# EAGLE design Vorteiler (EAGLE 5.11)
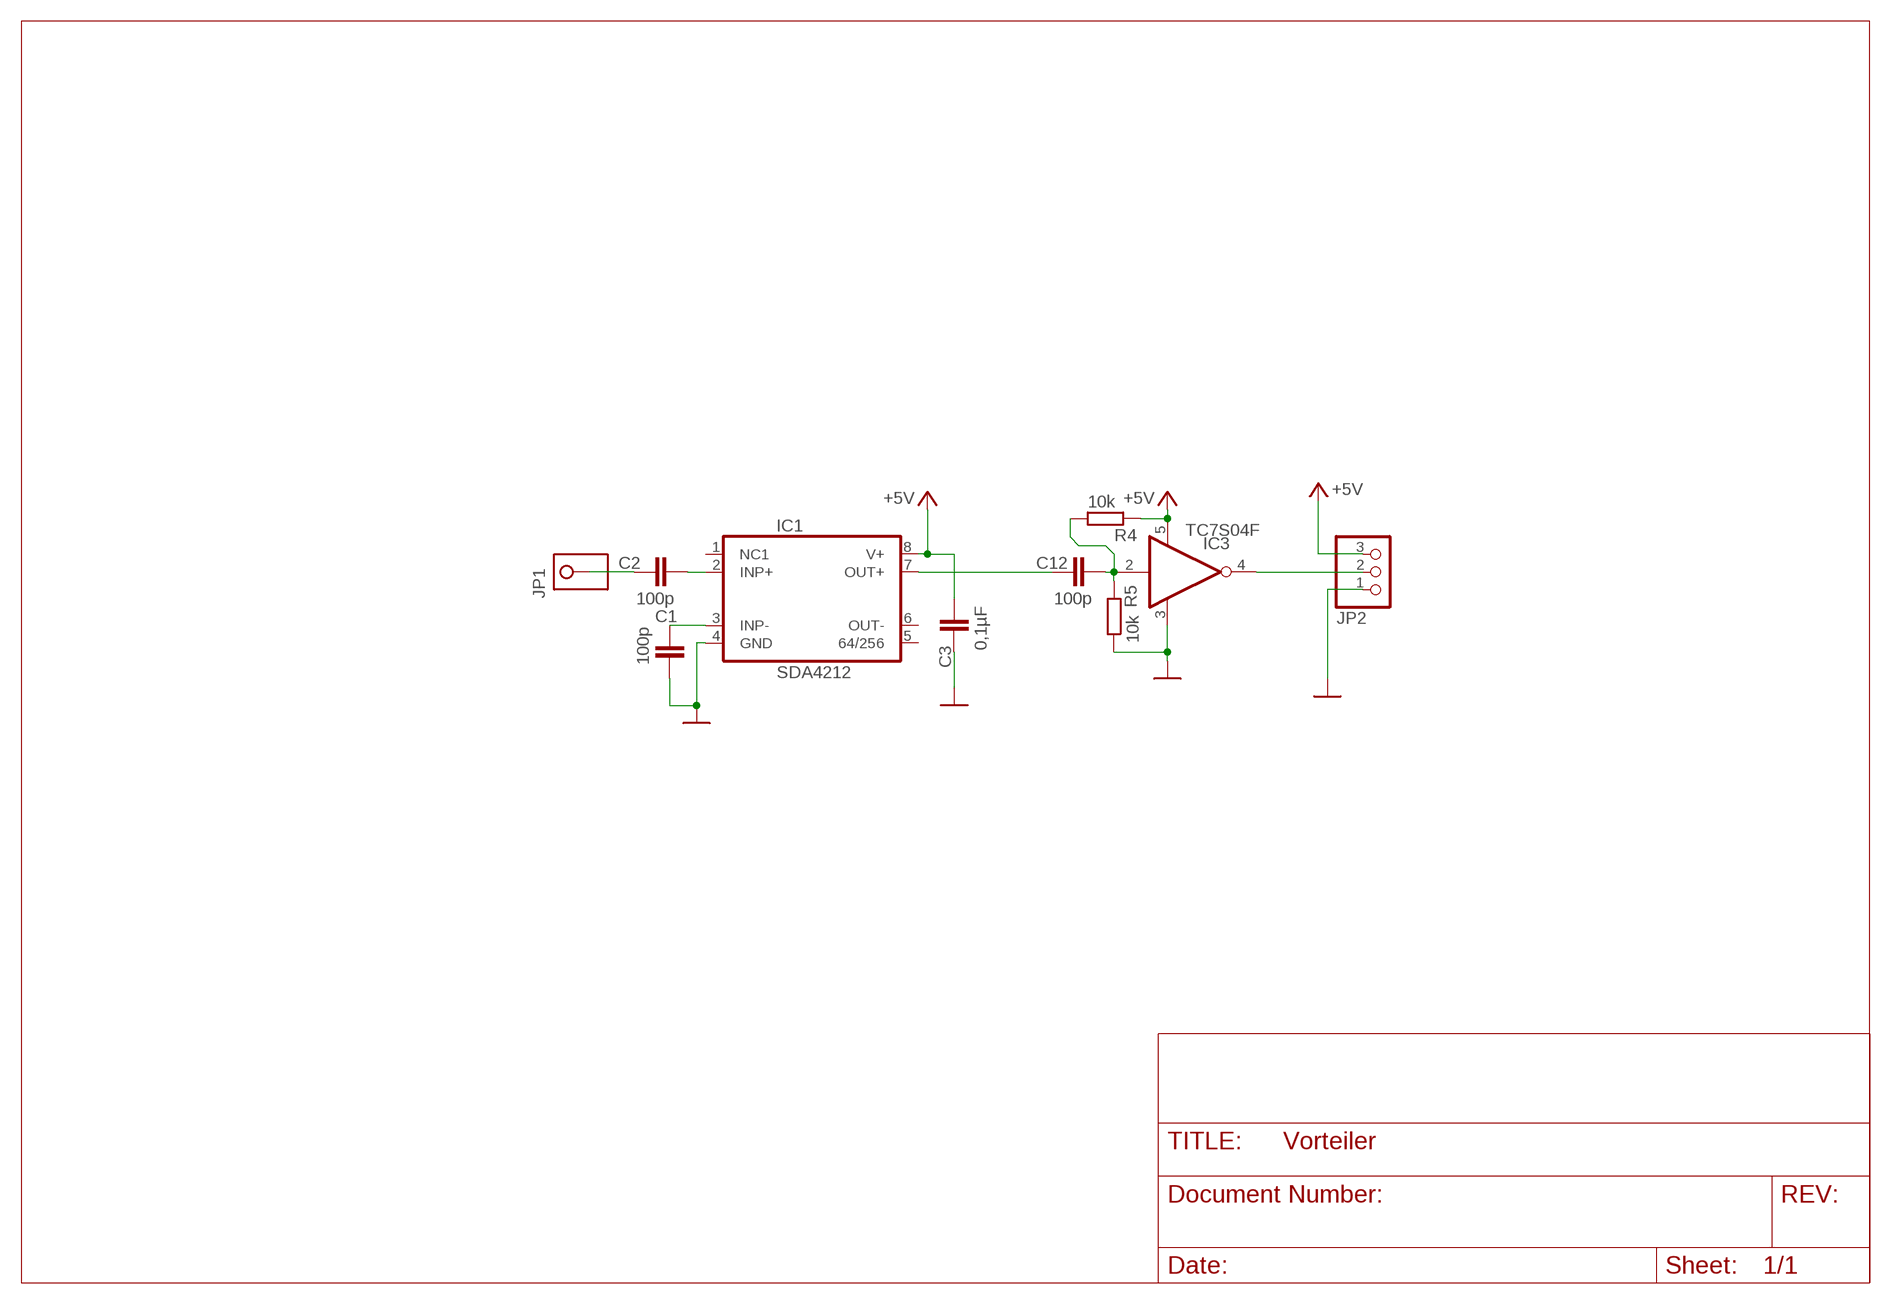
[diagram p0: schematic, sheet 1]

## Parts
C1  100p  C-EUC0805  [C0805]
C2  100p  C-EUC0805  [C0805]
C3  0,1µF  C-EUC0805  [C0805]
C12  100p  C-EUC0805  [C0805]
IC1  SDA4212  [DIL8]
IC3  TC7S04F  [SSOP5]
JP1  LÖTPUNKT1  [PUNKT1]
JP2  PINHD-1X03_2.54-90°  [1X03/90]
R4  10k  R-EU_R0805  [R0805]
R5  10k  R-EU_R0805  [R0805]

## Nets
+5V: C3.1 IC1.8(V+) IC3.5(VCC) JP2.3 R4.2
GND: C1.1 C3.2 IC1.4(GND) IC3.3(GND) JP2.1 R5.1
N$1: C12.2 IC1.7(OUT+)
N$2: C12.1 IC3.2(I) R4.1 R5.2
N$3: C1.2 IC1.3(INP-)
N$5: C2.1 IC1.2(INP+)
N$6: C2.2 JP1.P$1
N$7: IC3.4(O) JP2.2
Unconnected: IC1.1(NC1) IC1.5(64/256) IC1.6(OUT-)

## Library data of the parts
C1-C3 C12 = rcl:C-EU: CAPACITOR, European symbol
IC1 = 1Eigene:SDA4212
IC3 = 1Eigene:TC7S04F
JP1 = 1Eigene:LÖTPUNKT1
JP2 = pinhead-2:PINHD-1X03: PIN HEADER
R4 R5 = rcl:R-EU_: RESISTOR, European symbol

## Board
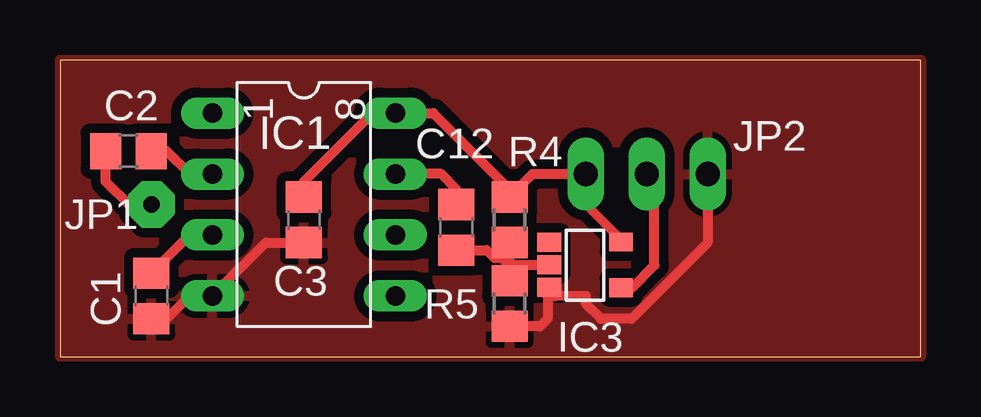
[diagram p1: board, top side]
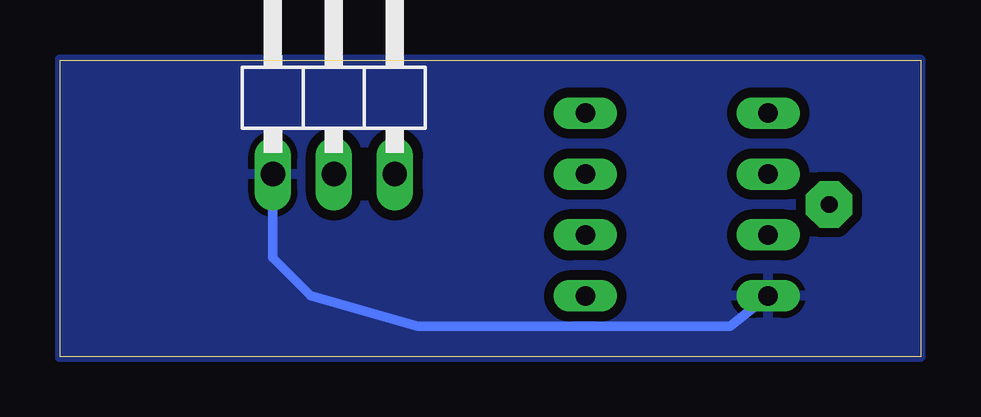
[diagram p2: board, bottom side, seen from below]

Size 35.86 x 12.37 mm. Coordinates in mm from the lower left corner, seen from the top.
Outline: 0,0 35.86,0 35.86,12.37 0,12.37 0,0
Copper layers (1*16): Top 0.035mm / dielectric 1.5mm / Bottom 0.035mm
Design rules "default *": minimum track width 0.4mm, minimum drill 0.7mm, track to track 0.4mm, track to pad 0.4mm, pad to pad 0.4mm, via to via 0.4mm, smd to smd 0.4mm, copper to edge 0mil, drill to drill 8mil, minimum pad ring 10mil, minimum via ring 8mil, stop-mask expansion 4mil, vias tented up to drill 0mil, thermal gap 10mil

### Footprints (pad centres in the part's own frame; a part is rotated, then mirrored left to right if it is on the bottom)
C0805 = smd 1.3 x 1.5: 1 -0.95,0; 2 0.95,0
DIL8 = drill 0.813 long: 1 -3.81,-3.81; 2 -1.27,-3.81; 3 1.27,-3.81; 4 3.81,-3.81; 5 3.81,3.81; 6 1.27,3.81; 7 -1.27,3.81; 8 -3.81,3.81
SSOP5 = smd 0.787 x 0.991: 1 0.965,1.518; 2 0.036,1.518; 3 -0.914,1.518; 4 -0.925,-1.469; 5 0.975,-1.469
PUNKT1 = drill 0.7 pad 1.93 octagon: P$1 0,0
1X03/90 = drill 1.016 long: 1 -2.54,-3.81; 2 0,-3.81; 3 2.54,-3.81
R0805 = smd 1.3 x 1.5: 1 -0.95,0; 2 0.95,0

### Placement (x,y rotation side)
C1  3.81,2.54 90 top
C2  2.86,8.57 180 top
C3  10.16,5.71 270 top
C12  16.51,5.4 90 top
IC1  10.16,6.35 270 top
IC3  21.91,3.81 90 top
JP1  3.81,6.35 0 top
JP2  24.45,11.43 0 bottom
R4  18.73,5.71 90 top
R5  18.73,2.22 90 top

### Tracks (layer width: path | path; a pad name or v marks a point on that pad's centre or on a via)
+5V
  Top 0.4: JP2.3 21.91,6.35 23.18,5.08 IC3.5
  Top 0.406: C3.1 10.16,7.3 13.02,10.16 IC1.8 15.56,10.16 18.6,7.12 18.73,7.12 R4.2 19.69,7.62 JP2.3
GND
  Top 0.4: C1.1 3.81,1.27 | 21.91,2.54 20.64,2.54 IC3.3
  Top 0.406: 20.64,2.54 20.32,2.54 20.32,1.59 20,1.27 R5.1 | C3.2 8.57,4.76 IC1.4 5.4,2.54 4.13,1.27 3.81,1.27 | 21.91,2.54 21.91,2.22 22.54,1.59 23.81,1.59 26.99,4.76 JP2.1
  Bottom 0.4: IC1.4 7.94,1.27 20.95,1.27 25.4,2.54 26.99,4.13 JP2.1
  pour Top: 0,12.38 35.88,12.38 35.88,0 0,0
  pour Bottom: 0,12.38 35.88,12.38 35.88,0 0,0
N$1
  Top 0.406: IC1.7 15.88,7.62 16.51,6.99 C12.2
N$2
  Top 0.406: 18.73,3.81 R4.1 | 18.73,3.81 R5.2 | IC3.2 18.77,3.85 18.73,3.81 | C12.1 17.78,4.45 18.1,4.13 18.41,4.13 18.73,3.81
N$3
  Top 0.406: C1.2 5.4,5.08 IC1.3
N$5
  Top 0.406: C2.1 4.45,8.57 5.4,7.62 IC1.2
N$6
  Top 0.406: JP1.P$1 2.86,6.35 1.91,7.3 C2.2
N$7
  Top 0.406: IC3.4 23.84,2.88 24.77,3.81 24.77,7.3 JP2.2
